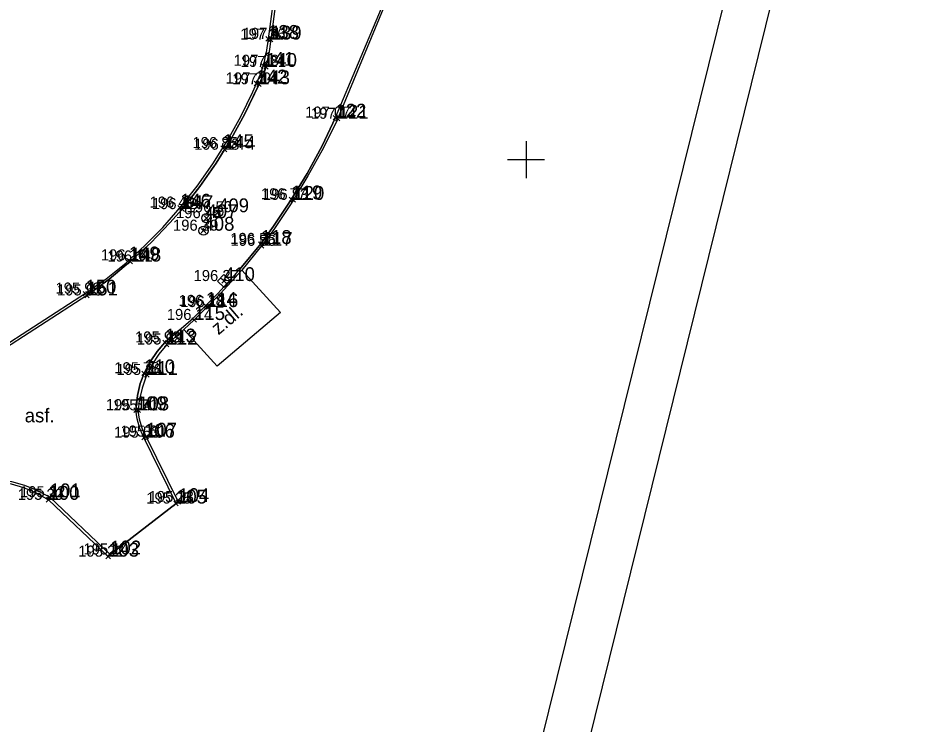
# Model space of a CAD drawing. Extents: x -706861 to -706379, y -1036456 to -1036201.
# Drawn here: x -706427.54 to -706379.24, y -1036380.6 to -1036342.31 of the extents above; entities that cross this region are included whole.
import ezdxf

# ---------------------------------------------------------------- set-up
doc = ezdxf.new("R2010")
doc.units = 0
for name, color, linetype in [('18_popisy', 7, 'Continuous'), ('29_vodovod', 7, 'Continuous'), ('30_kanalizace splašková', 7, 'Continuous'), ('40_plochy', 7, 'Continuous'), ('51_body polohopisu_značky', 7, 'Continuous'), ('52_body polohopisu_čísla', 7, 'Continuous'), ('53_body polohopisu_výšky', 7, 'Continuous'), ('54_body polohopisu_čísla nadbytečné pro kreslení', 7, 'Continuous'), ('5_rozhraní ploch', 7, 'Continuous'), ('60_mapový rám_legenda', 7, 'Continuous')]:
    doc.layers.add(name, color=color, linetype=linetype)

msp = doc.modelspace()

# ---------------------------------------------------------------- linework, layer by layer
at = {"layer": '29_vodovod'}
msp.add_circle((-706417.32, -1036353.17), 0.25, dxfattribs=at)
at = {"layer": '30_kanalizace splašková'}
msp.add_line((-706416.553, -1036356.409), (-706416.187, -1036356.751), dxfattribs=at)
msp.add_lwpolyline([(-706416.724, -1036356.593), (-706416.358, -1036356.934), (-706416.016, -1036356.568), (-706416.382, -1036356.226)], close=True, dxfattribs=at)
for centre in [(-706416.69, -1036352.85), (-706417.48, -1036353.85)]:
    msp.add_circle(centre, 0.25, dxfattribs=at)
at = {"layer": '40_plochy'}
for points in [[(-706413.05, -1036337.52), (-706413.84, -1036343.49), (-706413.94, -1036344.26), (-706414.03, -1036344.74), (-706414.21, -1036345.34), (-706414.47, -1036345.91), (-706415.24, -1036347.52), (-706415.99, -1036348.87), (-706416.8, -1036350.19), (-706417.68, -1036351.46), (-706418.63, -1036352.68), (-706419.3, -1036353.43), (-706420.34, -1036354.5), (-706421.44, -1036355.51), (-706422.6, -1036356.47), (-706423.8, -1036357.36), (-706431.36, -1036362.25)], [(-706427.88, -1036367.44), (-706427.19, -1036367.64), (-706426.52, -1036367.91), (-706425.81, -1036368.3), (-706422.54, -1036371.4), (-706418.97, -1036368.64), (-706420.71, -1036365.06), (-706420.93, -1036364.57), (-706421.08, -1036364.05), (-706421.14, -1036363.58), (-706421.06, -1036362.78), (-706420.91, -1036362.14), (-706420.68, -1036361.53), (-706420.38, -1036360.95), (-706420, -1036360.4), (-706419.57, -1036359.91), (-706418.04, -1036358.6), (-706416.71, -1036357.26), (-706415.51, -1036355.94), (-706414.38, -1036354.57), (-706413.68, -1036353.6), (-706412.74, -1036352.19), (-706411.86, -1036350.74), (-706411.06, -1036349.25), (-706410.33, -1036347.72), (-706407.83, -1036341.78)]]:
    msp.add_lwpolyline(points, dxfattribs=at)
msp.add_lwpolyline([(-706415.41, -1036355.99), (-706413.314, -1036358.279), (-706416.745, -1036361.195), (-706418.555, -1036359.197), (-706417.98, -1036358.68), (-706416.56, -1036357.26)], close=True, dxfattribs=at)
at = {"layer": '51_body polohopisu_značky'}
for points in [[(-706414.1, -1036343.57), (-706413.86, -1036343.33)], [(-706414.1, -1036343.33), (-706413.86, -1036343.57)], [(-706413.96, -1036343.61), (-706413.72, -1036343.37)], [(-706413.96, -1036343.37), (-706413.72, -1036343.61)], [(-706414.35, -1036345.03), (-706414.11, -1036344.79)], [(-706414.35, -1036344.79), (-706414.11, -1036345.03)], [(-706414.21, -1036345.09), (-706413.97, -1036344.85)], [(-706414.21, -1036344.85), (-706413.97, -1036345.09)], [(-706414.73, -1036345.99), (-706414.49, -1036345.75)], [(-706414.73, -1036345.75), (-706414.49, -1036345.99)], [(-706414.59, -1036346.03), (-706414.35, -1036345.79)], [(-706414.59, -1036345.79), (-706414.35, -1036346.03)], [(-706410.45, -1036347.84), (-706410.21, -1036347.6)], [(-706410.45, -1036347.6), (-706410.21, -1036347.84)], [(-706410.33, -1036347.9), (-706410.09, -1036347.66)], [(-706410.33, -1036347.66), (-706410.09, -1036347.9)], [(-706416.55, -1036349.49), (-706416.31, -1036349.25)], [(-706416.55, -1036349.25), (-706416.31, -1036349.49)], [(-706416.46, -1036349.58), (-706416.22, -1036349.34)], [(-706416.46, -1036349.34), (-706416.22, -1036349.58)], [(-706412.84, -1036352.27), (-706412.6, -1036352.03)], [(-706412.84, -1036352.03), (-706412.6, -1036352.27)], [(-706412.73, -1036352.3), (-706412.49, -1036352.06)], [(-706412.73, -1036352.06), (-706412.49, -1036352.3)], [(-706418.87, -1036352.72), (-706418.63, -1036352.48)], [(-706418.87, -1036352.48), (-706418.63, -1036352.72)], [(-706418.75, -1036352.8), (-706418.51, -1036352.56)], [(-706418.75, -1036352.56), (-706418.51, -1036352.8)], [(-706417.44, -1036353.29), (-706417.2, -1036353.05)], [(-706417.44, -1036353.05), (-706417.2, -1036353.29)], [(-706416.81, -1036352.97), (-706416.57, -1036352.73)], [(-706416.81, -1036352.73), (-706416.57, -1036352.97)], [(-706417.6, -1036353.97), (-706417.36, -1036353.73)], [(-706417.6, -1036353.73), (-706417.36, -1036353.97)], [(-706414.5, -1036354.69), (-706414.26, -1036354.45)], [(-706414.5, -1036354.45), (-706414.26, -1036354.69)], [(-706414.45, -1036354.79), (-706414.21, -1036354.55)], [(-706414.45, -1036354.55), (-706414.21, -1036354.79)], [(-706421.65, -1036355.58), (-706421.41, -1036355.34)], [(-706421.65, -1036355.34), (-706421.41, -1036355.58)], [(-706421.57, -1036355.64), (-706421.33, -1036355.4)], [(-706421.57, -1036355.4), (-706421.33, -1036355.64)], [(-706416.49, -1036356.7), (-706416.25, -1036356.46)], [(-706416.49, -1036356.46), (-706416.25, -1036356.7)], [(-706424, -1036357.38), (-706423.76, -1036357.14)], [(-706424, -1036357.14), (-706423.76, -1036357.38)], [(-706423.92, -1036357.48), (-706423.68, -1036357.24)], [(-706423.92, -1036357.24), (-706423.68, -1036357.48)], [(-706417.47, -1036358.05), (-706417.23, -1036357.81)], [(-706417.47, -1036357.81), (-706417.23, -1036358.05)], [(-706417.39, -1036358.11), (-706417.15, -1036357.87)], [(-706417.39, -1036357.87), (-706417.15, -1036358.11)], [(-706418.11, -1036358.81), (-706417.87, -1036358.57)], [(-706418.11, -1036358.57), (-706417.87, -1036358.81)], [(-706419.69, -1036360.03), (-706419.45, -1036359.79)], [(-706419.69, -1036359.79), (-706419.45, -1036360.03)], [(-706419.6, -1036360.14), (-706419.36, -1036359.9)], [(-706419.6, -1036359.9), (-706419.36, -1036360.14)], [(-706420.82, -1036361.7), (-706420.58, -1036361.46)], [(-706420.82, -1036361.46), (-706420.58, -1036361.7)], [(-706420.67, -1036361.79), (-706420.43, -1036361.55)], [(-706420.67, -1036361.55), (-706420.43, -1036361.79)], [(-706421.26, -1036363.7), (-706421.02, -1036363.46)], [(-706421.26, -1036363.46), (-706421.02, -1036363.7)], [(-706421.14, -1036363.71), (-706420.9, -1036363.47)], [(-706421.14, -1036363.47), (-706420.9, -1036363.71)], [(-706420.83, -1036365.19), (-706420.59, -1036364.95)], [(-706420.83, -1036364.95), (-706420.59, -1036365.19)], [(-706420.71, -1036365.13), (-706420.47, -1036364.89)], [(-706420.71, -1036364.89), (-706420.47, -1036365.13)], [(-706426, -1036368.56), (-706425.76, -1036368.32)], [(-706426, -1036368.32), (-706425.76, -1036368.56)], [(-706425.93, -1036368.42), (-706425.69, -1036368.18)], [(-706425.93, -1036368.18), (-706425.69, -1036368.42)], [(-706419.09, -1036368.76), (-706418.85, -1036368.52)], [(-706419.09, -1036368.52), (-706418.85, -1036368.76)], [(-706418.96, -1036368.68), (-706418.72, -1036368.44)], [(-706418.96, -1036368.44), (-706418.72, -1036368.68)], [(-706422.77, -1036371.64), (-706422.53, -1036371.4)], [(-706422.77, -1036371.4), (-706422.53, -1036371.64)], [(-706422.66, -1036371.52), (-706422.42, -1036371.28)], [(-706422.66, -1036371.28), (-706422.42, -1036371.52)]]:
    msp.add_lwpolyline(points, dxfattribs=at)
at = {"layer": '5_rozhraní ploch'}
msp.add_line((-706418.97, -1036368.64), (-706422.54, -1036371.4), dxfattribs=at)
for points in [[(-706410.33, -1036347.72), (-706407.83, -1036341.78), (-706407.42, -1036340.35), (-706406.21, -1036331), (-706405.21, -1036323.48), (-706404.51, -1036311.49)], [(-706410.21, -1036347.78), (-706407.73, -1036341.81), (-706407.3, -1036340.35), (-706406.08, -1036331.02), (-706405.11, -1036323.5), (-706404.42, -1036312.5), (-706404.35, -1036311.5), (-706404.51, -1036311.49)], [(-706412.06, -1036328.61), (-706412.3, -1036330.58), (-706412.93, -1036335.56), (-706413.18, -1036337.53), (-706413.98, -1036343.45), (-706414.08, -1036344.19)], [(-706411.93, -1036328.64), (-706412.15, -1036330.61), (-706412.82, -1036335.6), (-706413.05, -1036337.52), (-706413.84, -1036343.49), (-706413.94, -1036344.26)], [(-706414.61, -1036345.87), (-706414.35, -1036345.28), (-706414.17, -1036344.67), (-706414.08, -1036344.19)], [(-706414.47, -1036345.91), (-706414.21, -1036345.34), (-706414.03, -1036344.74), (-706413.94, -1036344.26)], [(-706418.75, -1036352.6), (-706417.83, -1036351.43), (-706416.97, -1036350.22), (-706416.18, -1036348.96), (-706415.46, -1036347.66), (-706414.81, -1036346.32), (-706414.61, -1036345.87)], [(-706418.63, -1036352.68), (-706417.68, -1036351.46), (-706416.8, -1036350.19), (-706415.99, -1036348.87), (-706415.24, -1036347.52), (-706414.57, -1036346.13), (-706414.47, -1036345.91)], [(-706410.33, -1036347.72), (-706411.06, -1036349.25), (-706411.86, -1036350.74), (-706412.74, -1036352.19), (-706413.68, -1036353.6), (-706414.38, -1036354.57)], [(-706410.21, -1036347.78), (-706410.98, -1036349.35), (-706411.82, -1036350.88), (-706412.73, -1036352.38), (-706413.71, -1036353.83), (-706414.33, -1036354.67)], [(-706423.88, -1036357.26), (-706422.76, -1036356.46), (-706421.68, -1036355.59), (-706420.66, -1036354.66), (-706419.69, -1036353.68), (-706418.75, -1036352.6)], [(-706423.8, -1036357.36), (-706422.6, -1036356.47), (-706421.44, -1036355.51), (-706420.34, -1036354.5), (-706419.3, -1036353.43), (-706418.63, -1036352.68)], [(-706414.38, -1036354.57), (-706415.51, -1036355.94), (-706416.71, -1036357.26), (-706418.04, -1036358.6)], [(-706414.33, -1036354.67), (-706415.41, -1036355.99), (-706416.56, -1036357.26), (-706417.98, -1036358.68)], [(-706415.41, -1036355.99), (-706413.314, -1036358.279), (-706416.745, -1036361.195), (-706418.555, -1036359.197)], [(-706423.88, -1036357.26), (-706431.43, -1036362.13), (-706434.81, -1036364.19), (-706437.64, -1036363.4)], [(-706423.8, -1036357.36), (-706431.36, -1036362.25), (-706434.8, -1036364.35), (-706437.61, -1036363.6)], [(-706419.57, -1036359.91), (-706418.04, -1036358.6)], [(-706419.47, -1036360.02), (-706418.555, -1036359.197), (-706417.98, -1036358.68)], [(-706419.57, -1036359.91), (-706420, -1036360.4), (-706420.38, -1036360.95), (-706420.68, -1036361.53), (-706420.91, -1036362.14), (-706421.06, -1036362.78), (-706421.13, -1036363.44), (-706421.14, -1036363.58)], [(-706419.47, -1036360.02), (-706419.91, -1036360.55), (-706420.28, -1036361.12), (-706420.58, -1036361.73), (-706420.81, -1036362.38), (-706420.96, -1036363.05), (-706421.02, -1036363.59)], [(-706420.71, -1036365.06), (-706420.93, -1036364.57), (-706421.08, -1036364.05), (-706421.14, -1036363.58)], [(-706420.58, -1036365.01), (-706420.8, -1036364.55), (-706420.95, -1036364.07), (-706421.02, -1036363.59)], [(-706418.97, -1036368.64), (-706420.71, -1036365.06)], [(-706418.97, -1036368.64), (-706418.84, -1036368.56), (-706420.58, -1036365.01)], [(-706430.72, -1036367.46), (-706430.01, -1036367.34), (-706429.3, -1036367.29), (-706428.58, -1036367.33), (-706427.88, -1036367.44), (-706427.19, -1036367.64), (-706426.52, -1036367.91), (-706425.81, -1036368.3)], [(-706430.71, -1036367.57), (-706430.01, -1036367.45), (-706429.31, -1036367.41), (-706428.61, -1036367.45), (-706427.91, -1036367.57), (-706427.23, -1036367.77), (-706426.58, -1036368.04), (-706425.97, -1036368.38), (-706425.88, -1036368.44)], [(-706425.88, -1036368.44), (-706422.65, -1036371.52), (-706422.54, -1036371.4)], [(-706425.81, -1036368.3), (-706422.54, -1036371.4)]]:
    msp.add_lwpolyline(points, dxfattribs=at)
at = {"layer": '60_mapový rám_legenda'}
for p, q in [((-706414.883, -1036455.51), (-706379.241, -1036311.351)), ((-706416.71, -1036452.483), (-706382.268, -1036313.178))]:
    msp.add_line(p, q, dxfattribs=at)
for points in [[(-706400, -1036349), (-706400, -1036350), (-706400, -1036351)], [(-706399, -1036350), (-706400, -1036350), (-706401, -1036350)]]:
    msp.add_lwpolyline(points, dxfattribs=at)

# ---------------------------------------------------------------- texts
at = {"layer": '18_popisy'}
msp.add_text('z.dl.', height=0.75, rotation=40.363, dxfattribs=at).set_placement((-706416.673, -1036359.532))
msp.add_text('asf.', height=0.75, dxfattribs=at).set_placement((-706427.17, -1036364.24))
at = {"layer": '52_body polohopisu_čísla'}
for s, p in [('138', (-706413.98, -1036343.45)), ('140', (-706414.09, -1036344.97)), ('142', (-706414.61, -1036345.87)), ('121', (-706410.21, -1036347.78)), ('145', (-706416.43, -1036349.37)), ('119', (-706412.72, -1036352.15)), ('146', (-706418.75, -1036352.6)), ('409', (-706416.69, -1036352.85)), ('408', (-706417.48, -1036353.85)), ('117', (-706414.33, -1036354.67)), ('149', (-706421.53, -1036355.46)), ('410', (-706416.37, -1036356.58)), ('151', (-706423.8, -1036357.36)), ('116', (-706417.27, -1036357.99)), ('113', (-706419.57, -1036359.91)), ('110', (-706420.7, -1036361.58)), ('108', (-706421.02, -1036363.59)), ('106', (-706420.71, -1036365.07)), ('100', (-706425.88, -1036368.44)), ('104', (-706418.84, -1036368.56)), ('103', (-706422.65, -1036371.52))]:
    msp.add_text(s, height=0.75, dxfattribs=at).set_placement(p)
at = {"layer": '53_body polohopisu_výšky'}
for s, p in [('197 36 ', (-706415.491, -1036343.49)), ('197 41 ', (-706415.357, -1036343.45)), ('197 28 ', (-706415.848, -1036344.91)), ('197 21 ', (-706415.467, -1036344.97)), ('197 20 ', (-706416.28, -1036345.87)), ('197 14 ', (-706415.918, -1036345.91)), ('197 07 ', (-706411.974, -1036347.72)), ('197 14 ', (-706411.658, -1036347.78)), ('196 85 ', (-706418.081, -1036349.37)), ('196 78 ', (-706417.991, -1036349.46)), ('196 77 ', (-706414.371, -1036352.15)), ('196 83 ', (-706414.261, -1036352.18)), ('196 49 ', (-706420.406, -1036352.6)), ('196 42 ', (-706420.281, -1036352.68)), ('196 45 ', (-706418.971, -1036353.17)), ('196 50 ', (-706418.393, -1036352.85)), ('196 39 ', (-706419.136, -1036353.85)), ('196 55 ', (-706416.031, -1036354.57)), ('196 56 ', (-706416.014, -1036354.67)), ('196 16 ', (-706423.044, -1036355.46)), ('196 11 ', (-706422.69, -1036355.52)), ('196 27 ', (-706418.021, -1036356.58)), ('195 99 ', (-706425.505, -1036357.26)), ('195 93 ', (-706425.42, -1036357.36)), ('196 18 ', (-706418.831, -1036357.93)), ('196 18 ', (-706418.751, -1036357.99)), ('196 14 ', (-706419.471, -1036358.69)), ('195 93 ', (-706421.19, -1036359.91)), ('195 98 ', (-706421.1, -1036360.02)), ('195 78 ', (-706422.318, -1036361.58)), ('195 86 ', (-706422.201, -1036361.67)), ('195 64 ', (-706422.775, -1036363.58)), ('195 71 ', (-706422.397, -1036363.59)), ('195 53 ', (-706422.328, -1036365.07)), ('195 61 ', (-706421.984, -1036365.01)), ('195 30 ', (-706427.55, -1036368.44)), ('195 22 ', (-706427.428, -1036368.3)), ('195 25 ', (-706420.588, -1036368.64)), ('195 33 ', (-706420.458, -1036368.56)), ('195 22 ', (-706424.268, -1036371.52)), ('195 14 ', (-706423.988, -1036371.4))]:
    msp.add_text(s, height=0.6, dxfattribs=at).set_placement(p)
at = {"layer": '54_body polohopisu_čísla nadbytečné pro kreslení'}
for s, p in [('139', (-706413.84, -1036343.49)), ('141', (-706414.23, -1036344.91)), ('143', (-706414.47, -1036345.91)), ('122', (-706410.33, -1036347.72)), ('144', (-706416.34, -1036349.46)), ('120', (-706412.61, -1036352.18)), ('147', (-706418.63, -1036352.68)), ('407', (-706417.32, -1036353.17)), ('118', (-706414.38, -1036354.57)), ('148', (-706421.45, -1036355.52)), ('150', (-706423.88, -1036357.26)), ('114', (-706417.35, -1036357.93)), ('115', (-706417.99, -1036358.69)), ('112', (-706419.48, -1036360.02)), ('111', (-706420.55, -1036361.67)), ('109', (-706421.14, -1036363.58)), ('107', (-706420.59, -1036365.01)), ('101', (-706425.81, -1036368.3)), ('105', (-706418.97, -1036368.64)), ('102', (-706422.54, -1036371.4))]:
    msp.add_text(s, height=0.75, dxfattribs=at).set_placement(p)

doc.saveas('drawing.dxf')
